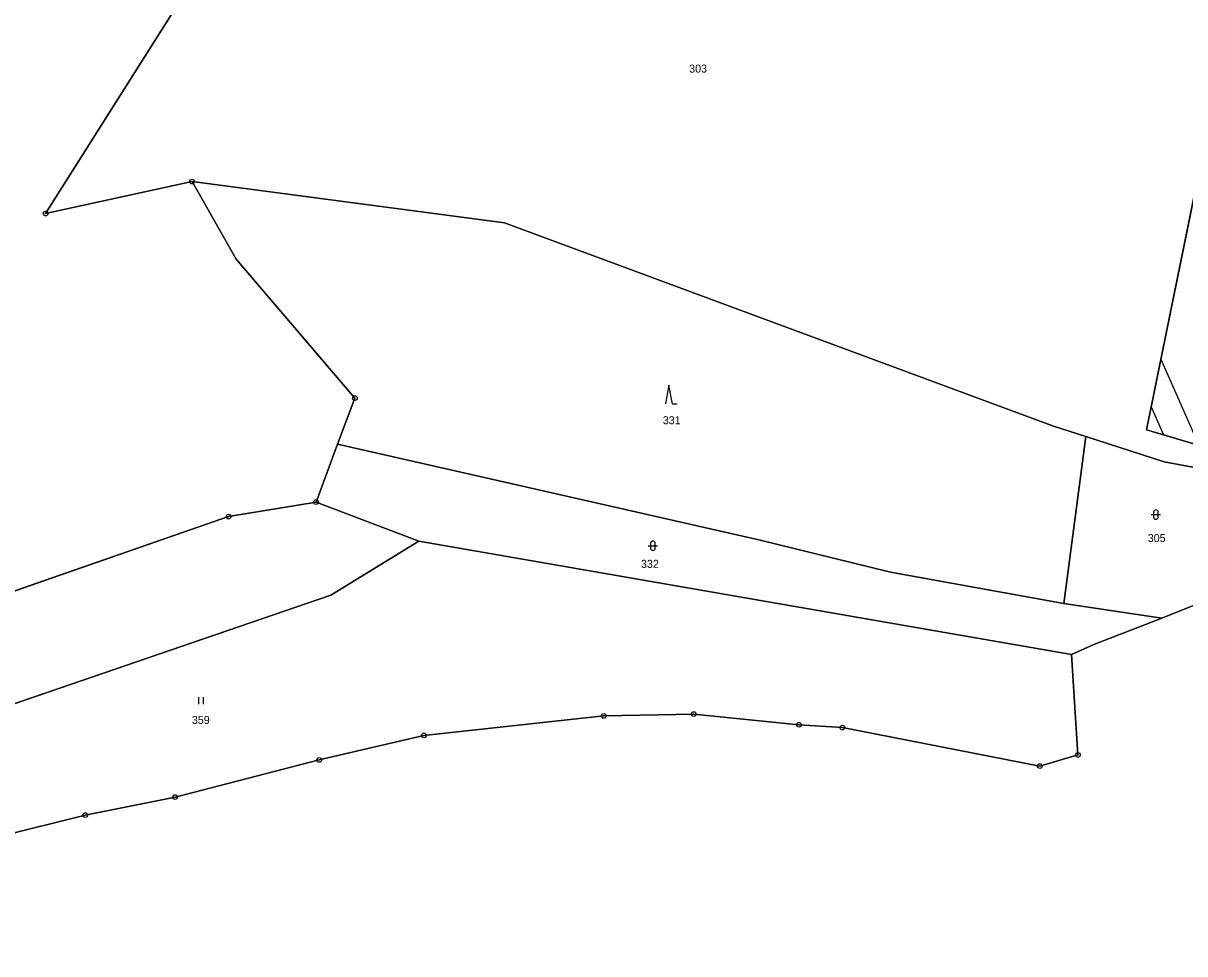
# Model space of a CAD drawing. Extents: x -689422 to -685210, y -987725 to -982160.
# Drawn here: x -686572.4 to -686325.7, y -987517 to -987319.2 of the extents above; entities that cross this region are included whole.
import ezdxf

# ---------------------------------------------------------------- set-up
doc = ezdxf.new("R2010")
doc.units = 0
for name, color, linetype in [('KN_Hranice obce', 7, 'Continuous'), ('KN_Hranice_katastrální území', 7, 'Continuous'), ('KN_Hranice_parcel', 7, 'Continuous'), ('KN_Parcelni cisla', 7, 'Continuous'), ('KN_Polygon parcely', 7, 'Continuous'), ('KN_POZEMKY_LESNI POZEMEK', 7, 'Continuous'), ('KN_POZEMKY_ORNA PUDA', 7, 'Continuous'), ('KN_POZEMKY_OSTATNI PLOCHA', 7, 'Continuous'), ('KN_POZEMKY_TTP', 7, 'Continuous'), ('KN_VYUZITI_27_ostatni plocha_neplodna puda', 7, 'Continuous'), ('KN_Věcná břemena k části', 7, 'Continuous'), ('KN_Značky bodu BP', 7, 'Continuous'), ('KN_Značky kultur', 7, 'Continuous')]:
    doc.layers.add(name, color=color, linetype=linetype)

msp = doc.modelspace()

# ---------------------------------------------------------------- linework, layer by layer
at = {"layer": 'KN_Hranice obce'}
msp.add_lwpolyline([(-686577.15, -987492), (-686559.2, -987487.52), (-686540.15, -987483.7), (-686509.52, -987475.79), (-686487.29, -987470.59), (-686449.08, -987466.44), (-686429.96, -987466.08), (-686407.61, -987468.32), (-686398.4, -987468.93), (-686356.47, -987477.12), (-686348.36, -987474.75), (-686349.75, -987453.38), (-686344.95, -987451.3), (-686330.52, -987445.68), (-686313.09, -987438.63)], dxfattribs=at)
at = {"layer": 'KN_Hranice_katastrální území'}
msp.add_lwpolyline([(-686577.15, -987492), (-686559.2, -987487.52), (-686540.15, -987483.7), (-686509.52, -987475.79), (-686487.29, -987470.59), (-686449.08, -987466.44), (-686429.96, -987466.08), (-686407.61, -987468.32), (-686398.4, -987468.93), (-686356.47, -987477.12), (-686348.36, -987474.75), (-686349.75, -987453.38), (-686344.95, -987451.3), (-686330.52, -987445.68), (-686313.09, -987438.63)], dxfattribs=at)
at = {"layer": 'KN_Hranice_parcel'}
for p, q in [((-686536.52, -987352.9), (-686470.17, -987361.65)), ((-686501.95, -987398.89), (-686505.62, -987408.73)), ((-686505.62, -987408.73), (-686510.19, -987420.99)), ((-686346.65, -987407.07), (-686351.38, -987442.55)), ((-686510.19, -987420.99), (-686488.35, -987429.34)), ((-686488.35, -987429.34), (-686349.75, -987453.38)), ((-686330.52, -987445.68), (-686313.09, -987438.63)), ((-686351.38, -987442.55), (-686330.52, -987445.68)), ((-686344.95, -987451.3), (-686330.52, -987445.68)), ((-686349.75, -987453.38), (-686344.95, -987451.3)), ((-686348.36, -987474.75), (-686349.75, -987453.38)), ((-686487.29, -987470.59), (-686449.08, -987466.44)), ((-686509.52, -987475.79), (-686487.29, -987470.59)), ((-686398.4, -987468.93), (-686356.47, -987477.12)), ((-686356.47, -987477.12), (-686348.36, -987474.75)), ((-686540.15, -987483.7), (-686509.52, -987475.79))]:
    msp.add_line(p, q, dxfattribs=at)
for points in [[(-686497.84, -987267.98), (-686522.78, -987288.63), (-686567.63, -987359.69), (-686536.52, -987352.9)], [(-686312.46, -987300.78), (-686333.82, -987405.66), (-686310.05, -987412.68), (-686279.46, -987417.1)], [(-686536.52, -987352.9), (-686527.13, -987369.36), (-686501.95, -987398.89)], [(-686470.17, -987361.65), (-686353.52, -987404.88), (-686346.65, -987407.07)], [(-686505.62, -987408.73), (-686416.14, -987429.06), (-686388.19, -987435.89), (-686351.38, -987442.55)], [(-686346.65, -987407.07), (-686330.04, -987412.47), (-686280.17, -987421.73)], [(-686510.19, -987420.99), (-686528.78, -987424.1), (-686611.59, -987452.89), (-686628.46, -987454.23), (-686641.79, -987453.43), (-686655.73, -987446.57), (-686667.87, -987435.8), (-686679.42, -987419.79)], [(-686696.41, -987484.73), (-686645.13, -987483.12), (-686630.56, -987481.14), (-686586.36, -987467.99), (-686507.07, -987440.78), (-686488.35, -987429.34)], [(-686449.08, -987466.44), (-686429.96, -987466.08), (-686407.61, -987468.32), (-686398.4, -987468.93)], [(-686593.79, -987498.53), (-686577.15, -987492), (-686559.2, -987487.52), (-686540.15, -987483.7)]]:
    msp.add_lwpolyline(points, dxfattribs=at)
at = {"layer": 'KN_Polygon parcely'}
for points in [[(-686280.17, -987421.73), (-686278.21, -987417.3), (-686279.46, -987417.1), (-686310.05, -987412.68), (-686333.82, -987405.66), (-686312.46, -987300.78), (-686384.77, -987295.86), (-686473.26, -987277.83), (-686485.19, -987277.7), (-686497.84, -987267.98), (-686522.78, -987288.63), (-686567.63, -987359.69), (-686536.52, -987352.9), (-686470.17, -987361.65), (-686353.52, -987404.88), (-686346.65, -987407.07), (-686330.04, -987412.47)], [(-686279.46, -987417.1), (-686262.76, -987365.79), (-686267.87, -987333.05), (-686272.11, -987307.92), (-686277.47, -987303.17), (-686312.46, -987300.78), (-686333.82, -987405.66), (-686310.05, -987412.68)], [(-686501.95, -987398.89), (-686505.62, -987408.73), (-686416.14, -987429.06), (-686388.19, -987435.89), (-686351.38, -987442.55), (-686346.65, -987407.07), (-686353.52, -987404.88), (-686470.17, -987361.65), (-686536.52, -987352.9), (-686527.13, -987369.36)], [(-686488.35, -987429.34), (-686349.75, -987453.38), (-686344.95, -987451.3), (-686330.52, -987445.68), (-686351.38, -987442.55), (-686388.19, -987435.89), (-686416.14, -987429.06), (-686505.62, -987408.73), (-686510.19, -987420.99)], [(-686280.17, -987421.73), (-686330.04, -987412.47), (-686346.65, -987407.07), (-686351.38, -987442.55), (-686330.52, -987445.68), (-686313.09, -987438.63), (-686292.96, -987426.07)], [(-686645.13, -987483.12), (-686630.56, -987481.14), (-686586.36, -987467.99), (-686507.07, -987440.78), (-686488.35, -987429.34), (-686510.19, -987420.99), (-686528.78, -987424.1), (-686611.59, -987452.89), (-686628.46, -987454.23), (-686641.79, -987453.43), (-686655.73, -987446.57), (-686667.87, -987435.8), (-686679.42, -987419.79), (-686681.67, -987420.61), (-686696.41, -987484.73)], [(-686356.47, -987477.12), (-686348.36, -987474.75), (-686349.75, -987453.38), (-686488.35, -987429.34), (-686507.07, -987440.78), (-686586.36, -987467.99), (-686630.56, -987481.14), (-686645.13, -987483.12), (-686696.41, -987484.73), (-686704.87, -987516.38), (-686681.88, -987517.01), (-686625.19, -987511.41), (-686593.79, -987498.53), (-686577.15, -987492), (-686559.2, -987487.52), (-686540.15, -987483.7), (-686509.52, -987475.79), (-686487.29, -987470.59), (-686449.08, -987466.44), (-686429.96, -987466.08), (-686407.61, -987468.32), (-686398.4, -987468.93)]]:
    msp.add_lwpolyline(points, close=True, dxfattribs=at)
msp.add_lwpolyline([(-686630.65, -987274.09), (-686666.55, -987370.98), (-686677.17, -987418.98), (-686679.42, -987419.79), (-686667.87, -987435.8), (-686655.73, -987446.57), (-686641.79, -987453.43), (-686628.46, -987454.23), (-686611.59, -987452.89), (-686528.78, -987424.1), (-686510.19, -987420.99), (-686505.62, -987408.73), (-686501.95, -987398.89), (-686527.13, -987369.36), (-686536.52, -987352.9), (-686567.63, -987359.69), (-686522.78, -987288.63)], dxfattribs=at)
at = {"layer": 'KN_POZEMKY_LESNI POZEMEK'}
for p, q in [((-686522.78, -987288.63), (-686567.63, -987359.69)), ((-686567.63, -987359.69), (-686536.52, -987352.9)), ((-686536.52, -987352.9), (-686527.13, -987369.36)), ((-686527.13, -987369.36), (-686536.52, -987352.9)), ((-686536.52, -987352.9), (-686470.17, -987361.65)), ((-686470.17, -987361.65), (-686353.52, -987404.88)), ((-686527.13, -987369.36), (-686501.95, -987398.89)), ((-686501.95, -987398.89), (-686527.13, -987369.36)), ((-686501.95, -987398.89), (-686505.62, -987408.73)), ((-686505.62, -987408.73), (-686501.95, -987398.89)), ((-686353.52, -987404.88), (-686346.65, -987407.07)), ((-686505.62, -987408.73), (-686510.19, -987420.99)), ((-686416.14, -987429.06), (-686505.62, -987408.73)), ((-686346.65, -987407.07), (-686351.38, -987442.55)), ((-686510.19, -987420.99), (-686528.78, -987424.1)), ((-686528.78, -987424.1), (-686611.59, -987452.89)), ((-686388.19, -987435.89), (-686416.14, -987429.06)), ((-686351.38, -987442.55), (-686388.19, -987435.89))]:
    msp.add_line(p, q, dxfattribs=at)
at = {"layer": 'KN_POZEMKY_ORNA PUDA'}
for p, q in [((-686567.63, -987359.69), (-686522.78, -987288.63)), ((-686312.46, -987300.78), (-686333.82, -987405.66)), ((-686536.52, -987352.9), (-686567.63, -987359.69)), ((-686470.17, -987361.65), (-686536.52, -987352.9)), ((-686353.52, -987404.88), (-686470.17, -987361.65)), ((-686346.65, -987407.07), (-686353.52, -987404.88)), ((-686333.82, -987405.66), (-686310.05, -987412.68)), ((-686330.04, -987412.47), (-686346.65, -987407.07)), ((-686280.17, -987421.73), (-686330.04, -987412.47))]:
    msp.add_line(p, q, dxfattribs=at)
at = {"layer": 'KN_POZEMKY_OSTATNI PLOCHA'}
for p, q in [((-686510.19, -987420.99), (-686505.62, -987408.73)), ((-686505.62, -987408.73), (-686416.14, -987429.06)), ((-686351.38, -987442.55), (-686346.65, -987407.07)), ((-686346.65, -987407.07), (-686330.04, -987412.47)), ((-686330.04, -987412.47), (-686280.17, -987421.73)), ((-686488.35, -987429.34), (-686510.19, -987420.99)), ((-686349.75, -987453.38), (-686488.35, -987429.34)), ((-686416.14, -987429.06), (-686388.19, -987435.89)), ((-686388.19, -987435.89), (-686351.38, -987442.55)), ((-686313.09, -987438.63), (-686330.52, -987445.68)), ((-686351.38, -987442.55), (-686330.52, -987445.68)), ((-686330.52, -987445.68), (-686351.38, -987442.55)), ((-686330.52, -987445.68), (-686344.95, -987451.3)), ((-686344.95, -987451.3), (-686349.75, -987453.38))]:
    msp.add_line(p, q, dxfattribs=at)
at = {"layer": 'KN_POZEMKY_TTP'}
for p, q in [((-686333.82, -987405.66), (-686312.46, -987300.78)), ((-686310.05, -987412.68), (-686333.82, -987405.66)), ((-686528.78, -987424.1), (-686510.19, -987420.99)), ((-686510.19, -987420.99), (-686488.35, -987429.34)), ((-686611.59, -987452.89), (-686528.78, -987424.1)), ((-686507.07, -987440.78), (-686488.35, -987429.34)), ((-686488.35, -987429.34), (-686507.07, -987440.78)), ((-686488.35, -987429.34), (-686349.75, -987453.38)), ((-686586.36, -987467.99), (-686507.07, -987440.78)), ((-686507.07, -987440.78), (-686586.36, -987467.99)), ((-686349.75, -987453.38), (-686348.36, -987474.75)), ((-686449.08, -987466.44), (-686487.29, -987470.59)), ((-686429.96, -987466.08), (-686449.08, -987466.44)), ((-686407.61, -987468.32), (-686429.96, -987466.08)), ((-686487.29, -987470.59), (-686509.52, -987475.79)), ((-686398.4, -987468.93), (-686407.61, -987468.32)), ((-686356.47, -987477.12), (-686398.4, -987468.93)), ((-686348.36, -987474.75), (-686356.47, -987477.12)), ((-686509.52, -987475.79), (-686540.15, -987483.7)), ((-686540.15, -987483.7), (-686559.2, -987487.52)), ((-686559.2, -987487.52), (-686577.15, -987492))]:
    msp.add_line(p, q, dxfattribs=at)
at = {"layer": 'KN_VYUZITI_27_ostatni plocha_neplodna puda'}
for p, q in [((-686510.19, -987420.99), (-686505.62, -987408.73)), ((-686505.62, -987408.73), (-686416.14, -987429.06)), ((-686351.38, -987442.55), (-686346.65, -987407.07)), ((-686346.65, -987407.07), (-686330.04, -987412.47)), ((-686330.04, -987412.47), (-686280.17, -987421.73)), ((-686488.35, -987429.34), (-686510.19, -987420.99)), ((-686349.75, -987453.38), (-686488.35, -987429.34)), ((-686416.14, -987429.06), (-686388.19, -987435.89)), ((-686388.19, -987435.89), (-686351.38, -987442.55)), ((-686313.09, -987438.63), (-686330.52, -987445.68)), ((-686351.38, -987442.55), (-686330.52, -987445.68)), ((-686330.52, -987445.68), (-686351.38, -987442.55)), ((-686330.52, -987445.68), (-686344.95, -987451.3)), ((-686344.95, -987451.3), (-686349.75, -987453.38))]:
    msp.add_line(p, q, dxfattribs=at)
at = {"layer": 'KN_Věcná břemena k části'}
msp.add_lwpolyline([(-686330.16, -987406.74), (-686322.61, -987408.97), (-686330.74, -987390.53), (-686332.82, -987400.75)], close=True, dxfattribs=at)
at = {"layer": 'KN_Značky bodu BP'}
for centre, radius in [((-686536.52, -987352.9), 0.5), ((-686536.52, -987352.9), 0.0303), ((-686567.63, -987359.69), 0.5), ((-686567.63, -987359.69), 0.0303), ((-686501.95, -987398.89), 0.5), ((-686501.95, -987398.89), 0.0303), ((-686510.19, -987420.99), 0.5), ((-686510.19, -987420.99), 0.0303), ((-686528.78, -987424.1), 0.5), ((-686528.78, -987424.1), 0.0303), ((-686429.96, -987466.08), 0.5), ((-686449.08, -987466.44), 0.5), ((-686449.08, -987466.44), 0.0303), ((-686429.96, -987466.08), 0.0303), ((-686407.61, -987468.32), 0.5), ((-686487.29, -987470.59), 0.5), ((-686487.29, -987470.59), 0.0303), ((-686407.61, -987468.32), 0.0303), ((-686398.4, -987468.93), 0.5), ((-686398.4, -987468.93), 0.0303), ((-686509.52, -987475.79), 0.5), ((-686348.36, -987474.75), 0.5), ((-686348.36, -987474.75), 0.0303), ((-686509.52, -987475.79), 0.0303), ((-686356.47, -987477.12), 0.5), ((-686356.47, -987477.12), 0.0303), ((-686540.15, -987483.7), 0.5), ((-686540.15, -987483.7), 0.0303), ((-686559.2, -987487.52), 0.5), ((-686559.2, -987487.52), 0.0303)]:
    msp.add_circle(centre, radius, dxfattribs=at)
at = {"layer": 'KN_Značky kultur'}
for p, q in [((-686435.23, -987396.13), (-686435.98, -987400.13)), ((-686434.48, -987400.13), (-686435.23, -987396.13)), ((-686434.48, -987400.13), (-686433.48, -987400.13)), ((-686332.8, -987423.65), (-686330.8, -987423.65)), ((-686332.3, -987423.15), (-686332.3, -987424.15)), ((-686331.3, -987424.15), (-686331.3, -987423.15)), ((-686439.63, -987430.3), (-686437.63, -987430.3)), ((-686439.13, -987429.8), (-686439.13, -987430.8)), ((-686438.13, -987430.8), (-686438.13, -987429.8)), ((-686535.1, -987463.96), (-686535.1, -987462.46)), ((-686534.1, -987463.96), (-686534.1, -987462.46))]:
    msp.add_line(p, q, dxfattribs=at)
for centre, start, end in [((-686331.8, -987423.15), 0, 180), ((-686331.8, -987424.15), 180, 359.9879), ((-686438.63, -987429.8), 0, 180), ((-686438.63, -987430.8), 180, 359.9879)]:
    msp.add_arc(centre, 0.5, start, end, dxfattribs=at)

# ---------------------------------------------------------------- texts
at = {"layer": 'KN_Parcelni cisla'}
for s, p in [('303', (-686430.94, -987329.72)), ('331', (-686436.54, -987404.46)), ('305', (-686333.53, -987429.5)), ('332', (-686441.17, -987434.98)), ('359', (-686536.57, -987468.16))]:
    msp.add_text(s, height=1.7, dxfattribs=at).set_placement(p)

doc.saveas('drawing.dxf')
